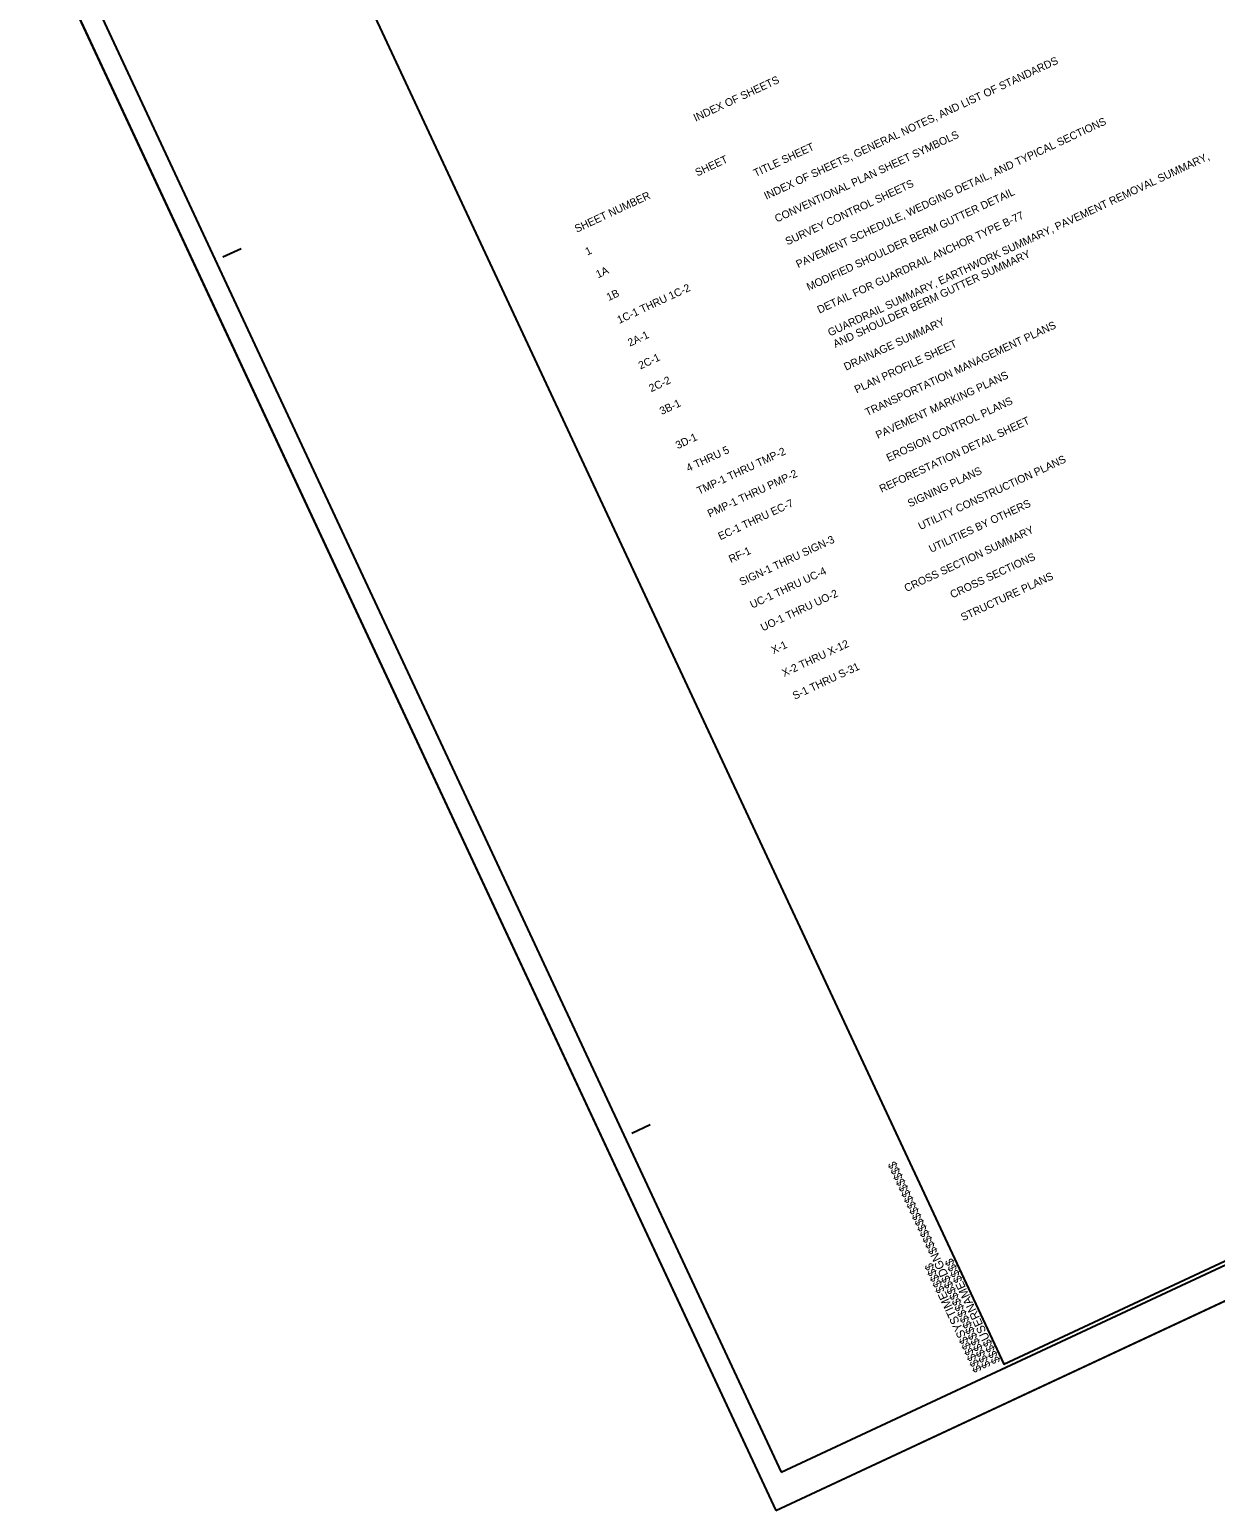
# Model space of a CAD drawing. Extents: x 2321368 to 2323356, y 919896 to 921600.
# Drawn here: x 2321368 to 2322104, y 919896 to 920814 of the extents above; entities that cross this region are included whole.
import ezdxf

# ---------------------------------------------------------------- set-up
doc = ezdxf.new("R2010")
doc.units = 0
for name, color, linetype in [('Default', 7, 'Continuous'), ('Sheet Cutting Line CELL', 7, 'Continuous'), ('Sheet Plan CELL', 7, 'Continuous'), ('Sheet Plot Border Inside CELL', 7, 'Continuous'), ('Sheet Plot Border Outside CELL', 7, 'Continuous')]:
    doc.layers.add(name, color=color, linetype=linetype)

msp = doc.modelspace()

# ---------------------------------------------------------------- linework, layer by layer
at = {"layer": 'Sheet Cutting Line CELL'}
for p, q in [((2321367.8, 920887.79), (2321830.89, 919895.53)), ((2321830.89, 919895.53), (2323356.43, 920607.51))]:
    msp.add_line(p, q, dxfattribs=at)
at = {"layer": 'Sheet Plan CELL'}
for p, q in [((2321487.73, 920673.39), (2321499.06, 920678.68)), ((2321741.48, 920129.69), (2321752.8, 920134.97)), ((2321972.26, 919986.34), (2321972.26, 919986.34))]:
    msp.add_line(p, q, dxfattribs=at)
msp.add_lwpolyline([(2322887.45, 921572.19), (2321528.2, 920937.82), (2321972.26, 919986.34), (2323331.51, 920620.71)], close=True, dxfattribs=at)
at = {"layer": 'Sheet Plot Border Inside CELL'}
msp.add_lwpolyline([(2321834.22, 919919.15), (2323343.9, 920623.73), (2322897.72, 921579.74), (2321388.04, 920875.16)], close=True, dxfattribs=at)
at = {"layer": 'Sheet Plot Border Outside CELL'}
msp.add_lwpolyline([(2321830.89, 919895.53), (2323356.43, 920607.51), (2322893.34, 921599.76), (2321367.8, 920887.79)], close=True, dxfattribs=at)

# ---------------------------------------------------------------- texts
at = {"layer": 'Default'}
for s, p in [('INDEX OF SHEETS, GENERAL NOTES, AND LIST OF STANDARDS', (2321824.9, 920708.8)), ('INDEX OF SHEETS', (2321781.11, 920757.23)), ('PAVEMENT SCHEDULE, WEDGING DETAIL, AND TYPICAL SECTIONS', (2321844.69, 920666.4)), ('TITLE SHEET', (2321818.3, 920722.94)), ('CONVENTIONAL PLAN SHEET SYMBOLS', (2321831.49, 920694.67)), ('              SHEET', (2321759.51, 920712.72)), ('GUARDRAIL SUMMARY, EARTHWORK SUMMARY, PAVEMENT REMOVAL SUMMARY, ', (2321864.48, 920623.99)), ('SURVEY CONTROL SHEETS', (2321838.09, 920680.53)), ('SHEET NUMBER', (2321707.31, 920688.36)), ('MODIFIED SHOULDER BERM GUTTER DETAIL', (2321851.29, 920652.26)), ('DETAIL FOR GUARDRAIL ANCHOR TYPE B-77', (2321857.88, 920638.12)), ('1', (2321713.91, 920674.22)), ('AND SHOULDER BERM GUTTER SUMMARY', (2321867.78, 920616.92)), ('1A', (2321720.51, 920660.08)), ('1B', (2321727.1, 920645.95)), ('1C-1 THRU 1C-2', (2321733.7, 920631.81)), ('DRAINAGE SUMMARY', (2321874.38, 920602.78)), ('2A-1', (2321740.3, 920617.68)), ('TRANSPORTATION MANAGEMENT PLANS', (2321887.57, 920574.51)), ('PLAN PROFILE SHEET', (2321880.98, 920588.65)), ('2C-1', (2321746.9, 920603.54)), ('2C-2', (2321753.49, 920589.4)), ('PAVEMENT MARKING PLANS', (2321894.17, 920560.37)), ('3B-1', (2321760.09, 920575.27)), ('EROSION CONTROL PLANS', (2321900.77, 920546.24)), ('    REFORESTATION DETAIL SHEET', (2321889.97, 920523.98)), ('3D-1', (2321769.99, 920554.06)), ('4 THRU 5', (2321776.58, 920539.93)), ('TMP-1 THRU TMP-2  ', (2321783.18, 920525.79)), ('SIGNING PLANS', (2321913.96, 920517.96)), ('UTILITY CONSTRUCTION PLANS', (2321920.56, 920503.83)), ('PMP-1 THRU PMP-2 ', (2321789.78, 920511.65)), ('EC-1 THRU EC-7', (2321796.38, 920497.52)), ('UTILITIES BY OTHERS', (2321927.16, 920489.69)), ('        CROSS SECTION SUMMARY', (2321898.96, 920459.32)), ('SIGN-1 THRU SIGN-3', (2321809.57, 920469.25)), ('RF-1 ', (2321802.97, 920483.38)), ('CROSS SECTIONS', (2321940.35, 920461.42)), ('UC-1 THRU UC-4', (2321816.17, 920455.11)), ('STRUCTURE PLANS', (2321946.95, 920447.28)), ('UO-1 THRU UO-2', (2321822.77, 920440.97)), ('X-1 ', (2321829.36, 920426.84)), ('X-2 THRU X-12', (2321835.96, 920412.7)), ('S-1 THRU S-31 ', (2321842.56, 920398.56))]:
    msp.add_text(s, height=4.8, rotation=25.01869, dxfattribs=at).set_placement(p)
at = {"layer": 'Sheet Plan CELL'}
for s, p in [('$$$$$$$$$$$$$$$$DGN$$$$$$$$$$$$$$$$', (2321964.33, 919985.24)), ('$$$$$$SYSTIME$$$$$', (2321958.84, 919982.68)), ('$$$$USERNAME$$$$', (2321970.28, 919988.03))]:
    msp.add_text(s, height=5.25, rotation=115.01869, dxfattribs=at).set_placement(p)

doc.saveas('drawing.dxf')
